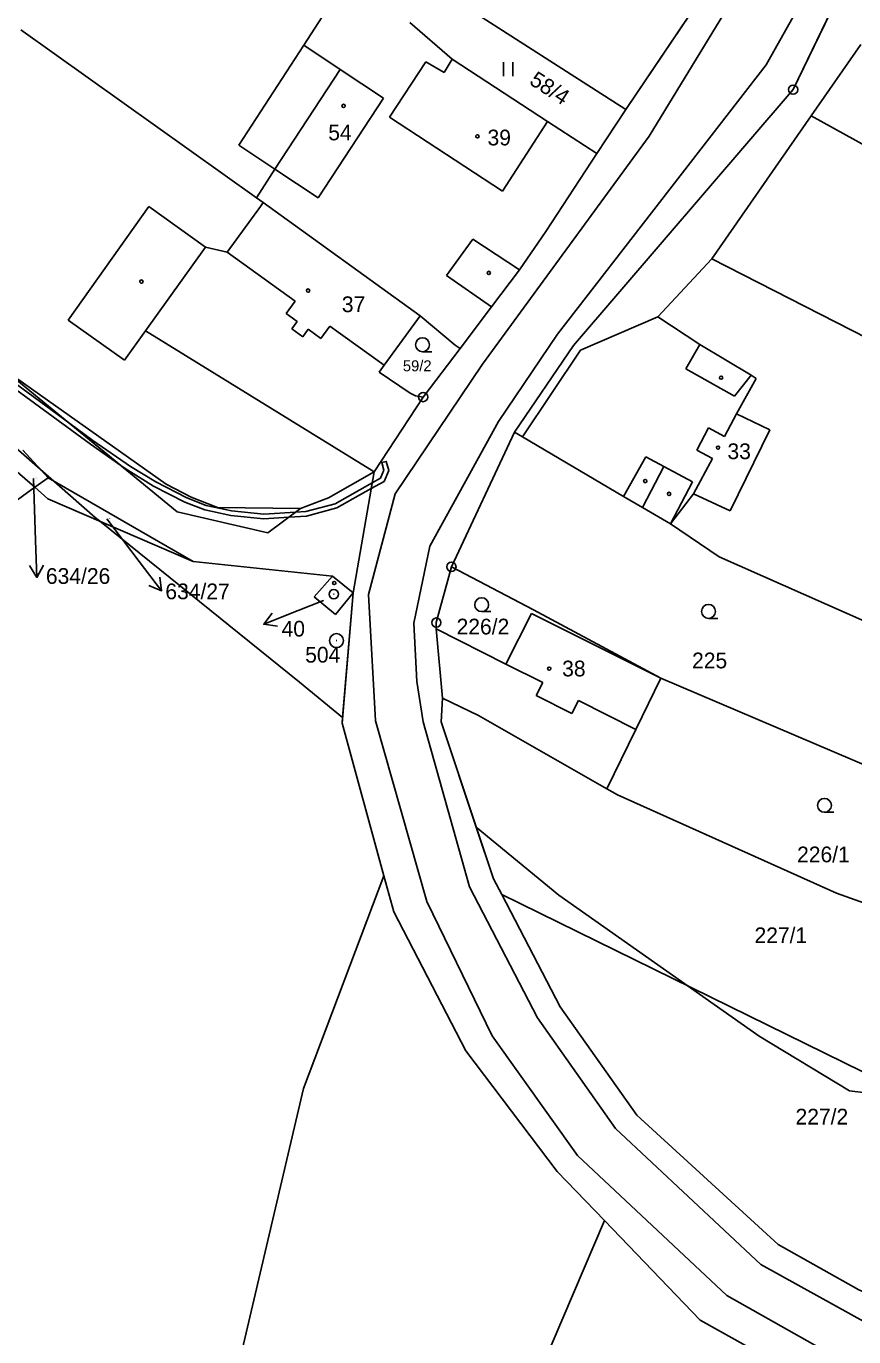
# Model space of a CAD drawing. Extents: x -743888 to -742027, y -1128394 to -1126768.
# Drawn here: x -743087.8 to -742998.5, y -1127789.2 to -1127647.7 of the extents above; entities that cross this region are included whole.
import ezdxf

# ---------------------------------------------------------------- set-up
doc = ezdxf.new("R2010")
doc.units = 0
for name, color, linetype in [('Vrstva 1', 7, 'Continuous'), ('Vrstva 16', 7, 'Continuous'), ('Vrstva 17', 7, 'Continuous'), ('Vrstva 18', 7, 'Continuous'), ('Vrstva 19', 7, 'Continuous'), ('Vrstva 24', 7, 'Continuous'), ('Vrstva 25', 7, 'Continuous'), ('Vrstva 3', 7, 'Continuous'), ('Vrstva 30', 7, 'Continuous'), ('Vrstva 37', 7, 'Continuous'), ('Vrstva 4', 7, 'Continuous'), ('Vrstva 52', 7, 'Continuous'), ('Vrstva 6', 7, 'Continuous')]:
    doc.layers.add(name, color=color, linetype=linetype)

msp = doc.modelspace()

# ---------------------------------------------------------------- linework, layer by layer
at = {"layer": 'Vrstva 1'}
for points in [[(-743005.02, -1127654.54), (-742990.11, -1127623.65)], [(-743023.07, -1127656.68), (-743006.21, -1127631.58)], [(-743057.84, -1127649.75), (-743053.43, -1127642.86)], [(-743041.39, -1127644.94), (-743023.07, -1127656.68)], [(-743088.43, -1127648.09), (-743062.98, -1127666.21)], [(-743046.41, -1127647.29), (-743041.85, -1127651.26)], [(-743064.89, -1127660.55), (-743057.84, -1127649.75)], [(-743057.84, -1127649.75), (-743053.93, -1127652.35)], [(-743003.07, -1127657.38), (-742997.69, -1127649.67)], [(-743053.93, -1127652.35), (-743049.27, -1127655.45)], [(-743041.85, -1127651.26), (-743031.54, -1127657.97)], [(-743028.72, -1127682.17), (-743005.02, -1127654.54)], [(-743056.31, -1127666.21), (-743049.27, -1127655.45)], [(-743026.2, -1127661.44), (-743023.07, -1127656.68)], [(-743031.54, -1127657.97), (-743026.2, -1127661.44)], [(-743013.81, -1127672.8), (-743003.07, -1127657.38)], [(-743064.89, -1127660.55), (-743060.97, -1127663.13)], [(-743031.72, -1127669.85), (-743026.2, -1127661.44)], [(-743062.98, -1127666.21), (-743060.97, -1127663.13)], [(-743060.97, -1127663.13), (-743056.31, -1127666.21)], [(-743062.98, -1127666.21), (-743062.24, -1127666.73)], [(-743062.54, -1127667.14), (-743062.24, -1127666.73)], [(-743062.24, -1127666.73), (-743045.29, -1127678.95)], [(-743083.3, -1127679.41), (-743074.6, -1127667.14)], [(-743074.6, -1127667.14), (-743068.46, -1127671.55)], [(-743066.13, -1127672.07), (-743062.54, -1127667.14)], [(-743034.56, -1127673.98), (-743031.72, -1127669.85)], [(-743068.46, -1127671.55), (-743066.13, -1127672.07)], [(-743019.62, -1127679.08), (-743013.81, -1127672.8)], [(-743013.81, -1127672.8), (-742970.18, -1127695.1)], [(-743037.58, -1127678), (-743034.56, -1127673.98)], [(-743040.96, -1127682.5), (-743037.58, -1127678)], [(-743083.3, -1127679.41), (-743077.21, -1127683.74)], [(-743049.19, -1127684.3), (-743045.58, -1127679.36)], [(-743045.58, -1127679.36), (-743045.29, -1127678.95)], [(-743045.29, -1127678.95), (-743041.53, -1127682.11)], [(-743027.99, -1127682.66), (-743019.62, -1127679.08)], [(-743019.62, -1127679.08), (-743015.08, -1127682.06)], [(-743077.21, -1127683.74), (-743074.95, -1127680.59)], [(-743074.95, -1127680.59), (-743050.26, -1127695.79)], [(-743041.53, -1127682.11), (-743040.96, -1127682.5)], [(-743035.1, -1127691.53), (-743028.72, -1127682.17)], [(-743015.08, -1127682.06), (-743009.56, -1127685.38)], [(-743044.97, -1127687.73), (-743040.96, -1127682.5)], [(-743034.24, -1127692.03), (-743027.99, -1127682.66)], [(-743049.72, -1127685.03), (-743049.19, -1127684.3)], [(-743049.72, -1127685.03), (-743046.39, -1127687.31)], [(-743011.13, -1127689.55), (-743009, -1127685.72)], [(-743009.56, -1127685.38), (-743009, -1127685.72)], [(-743050.26, -1127695.79), (-743044.97, -1127687.73)], [(-743046.39, -1127687.31), (-743045.79, -1127687.59)], [(-743045.79, -1127687.59), (-743044.97, -1127687.73)], [(-743011.13, -1127689.55), (-743007.52, -1127691.27)], [(-743041.92, -1127706.05), (-743035.1, -1127691.53)], [(-743035.1, -1127691.53), (-743034.24, -1127692.03)], [(-743034.24, -1127692.03), (-743023.34, -1127698.47)], [(-743011.82, -1127700.03), (-743007.52, -1127691.27)], [(-743089.62, -1127695.12), (-743086.91, -1127697.47)], [(-743055.21, -1127698.61), (-743050.26, -1127695.79)], [(-743052.52, -1127708.86), (-743050.26, -1127695.79)], [(-743086.91, -1127697.47), (-743085.49, -1127698.7)], [(-743085.49, -1127698.7), (-743069.79, -1127705.5)], [(-743058.22, -1127699.76), (-743055.21, -1127698.61)], [(-743023.34, -1127698.47), (-743021.3, -1127699.65)], [(-743018.27, -1127701.4), (-743015.78, -1127698.17)], [(-743015.78, -1127698.17), (-743011.82, -1127700.03)], [(-743021.3, -1127699.65), (-743018.27, -1127701.4)], [(-743018.27, -1127701.4), (-743013, -1127704.97)], [(-743069.79, -1127705.5), (-743054.75, -1127707.06)], [(-743043.55, -1127712.08), (-743041.92, -1127706.05)], [(-743041.92, -1127706.05), (-743033.05, -1127710.69)], [(-743013, -1127704.97), (-742980.63, -1127719.3)], [(-743056.75, -1127709.3), (-743054.75, -1127707.06)], [(-743054.75, -1127707.06), (-743052.52, -1127708.86)], [(-743054.42, -1127711.2), (-743052.52, -1127708.86)], [(-743053.72, -1127722.94), (-743052.52, -1127708.86)], [(-743056.75, -1127709.3), (-743054.42, -1127711.2)], [(-743036.05, -1127716.56), (-743033.26, -1127711.09)], [(-743033.26, -1127711.09), (-743019.3, -1127718.08)], [(-743033.05, -1127710.69), (-743019.3, -1127718.08)], [(-743043.57, -1127712.76), (-743043.55, -1127712.08)], [(-743043.57, -1127712.76), (-743042.89, -1127720.23)], [(-743043.57, -1127712.76), (-743036.05, -1127716.56)], [(-743022, -1127723.61), (-743019.3, -1127718.08)], [(-743019.3, -1127718.08), (-742986.19, -1127732.18)], [(-743043.04, -1127722.81), (-743042.89, -1127720.23)], [(-743042.89, -1127720.23), (-743039.01, -1127722.1)], [(-743053.72, -1127722.94), (-743049.21, -1127739.41)], [(-743043.04, -1127722.81), (-743037.36, -1127739.74)], [(-743039.01, -1127722.1), (-743025.14, -1127730.02)], [(-743025.14, -1127730.02), (-743022, -1127723.61)], [(-743025.14, -1127730.02), (-743023.98, -1127730.68)], [(-743023.98, -1127730.68), (-743000.34, -1127741.31)], [(-743049.21, -1127739.41), (-743048.14, -1127743.3)], [(-743037.36, -1127739.74), (-743036.47, -1127741.45)], [(-743036.47, -1127741.45), (-743030.16, -1127753.57)], [(-743000.34, -1127741.31), (-742982, -1127747.83)], [(-743048.14, -1127743.3), (-743040.35, -1127758.3)], [(-743030.16, -1127753.57), (-743021.89, -1127765.25)], [(-743040.35, -1127758.3), (-743030.5, -1127771.33)], [(-743021.89, -1127765.25), (-743006.65, -1127779.24)], [(-743030.5, -1127771.33), (-743025.38, -1127776.65)], [(-743025.38, -1127776.65), (-743015.05, -1127787.39)], [(-743006.65, -1127779.24), (-742997.92, -1127784.13)], [(-743015.05, -1127787.39), (-743011.33, -1127789.48)]]:
    msp.add_lwpolyline(points, dxfattribs=at)
at = {"layer": 'Vrstva 16'}
for p, q in [((-743085.97, -1127705.87), (-743086.68, -1127707.2)), ((-743073.4, -1127707.16), (-743073.21, -1127708.65)), ((-743060.7, -1127712.48), (-743062.19, -1127712.26))]:
    msp.add_line(p, q, dxfattribs=at)
for points in [[(-743087.06, -1127696.52), (-743086.82, -1127703.2)], [(-743079.13, -1127700.88), (-743075.63, -1127705.47)], [(-743086.82, -1127703.2), (-743086.68, -1127707.2), (-743087.47, -1127705.93)], [(-743075.63, -1127705.47), (-743073.21, -1127708.65), (-743074.59, -1127708.07)], [(-743055.74, -1127709.69), (-743058.47, -1127710.78)], [(-743058.47, -1127710.78), (-743062.19, -1127712.26), (-743061.26, -1127711.08)]]:
    msp.add_lwpolyline(points, dxfattribs=at)
at = {"layer": 'Vrstva 24'}
for p, q in [((-743005.07, -1127654.54), (-743004.97, -1127654.54)), ((-743045.02, -1127687.73), (-743044.92, -1127687.73)), ((-743041.97, -1127706.05), (-743041.87, -1127706.05)), ((-743054.67, -1127709.01), (-743054.57, -1127709.01)), ((-743043.6, -1127712.08), (-743043.5, -1127712.08)), ((-743054.38, -1127714.03), (-743054.28, -1127714.03))]:
    msp.add_line(p, q, dxfattribs=at)
for centre, radius in [((-743005.02, -1127654.54), 0.499), ((-743044.97, -1127687.73), 0.499), ((-743041.92, -1127706.05), 0.499), ((-743054.62, -1127709.01), 0.499), ((-743043.55, -1127712.08), 0.499), ((-743054.33, -1127714.03), 0.756)]:
    msp.add_circle(centre, radius, dxfattribs=at)
at = {"layer": 'Vrstva 25'}
for p, q in [((-743036.3, -1127651.57), (-743036.3, -1127653.07)), ((-743035.3, -1127653.07), (-743035.3, -1127651.57)), ((-743045.04, -1127682.83), (-743044.04, -1127682.83)), ((-743038.65, -1127710.9), (-743037.65, -1127710.9)), ((-743014.16, -1127711.62), (-743013.16, -1127711.62)), ((-743001.64, -1127732.56), (-743000.64, -1127732.56))]:
    msp.add_line(p, q, dxfattribs=at)
for centre, radius in [((-743053.56, -1127656.29), 0.175), ((-743039.11, -1127659.58), 0.175), ((-743075.39, -1127675.26), 0.175), ((-743037.88, -1127674.33), 0.175), ((-743057.4, -1127676.23), 0.175), ((-743045.04, -1127682.08), 0.75), ((-743012.8, -1127685.64), 0.175), ((-743013.13, -1127693.19), 0.175), ((-743020.99, -1127696.8), 0.175), ((-743018.41, -1127698.19), 0.175), ((-743054.57, -1127707.81), 0.175), ((-743038.65, -1127710.15), 0.75), ((-743014.16, -1127710.87), 0.75), ((-743031.36, -1127717.05), 0.175), ((-743001.64, -1127731.81), 0.75)]:
    msp.add_circle(centre, radius, dxfattribs=at)
at = {"layer": 'Vrstva 3'}
for points in [[(-743060.97, -1127663.13), (-743053.93, -1127652.35)], [(-743053.93, -1127652.35), (-743049.27, -1127655.45)], [(-743048.61, -1127657.52), (-743044.69, -1127651.52)], [(-743044.69, -1127651.52), (-743042.7, -1127652.7)], [(-743042.7, -1127652.7), (-743041.85, -1127651.26)], [(-743041.85, -1127651.26), (-743031.54, -1127657.97)], [(-743056.31, -1127666.21), (-743049.27, -1127655.45)], [(-743048.61, -1127657.52), (-743036.42, -1127665.5)], [(-743036.42, -1127665.5), (-743031.54, -1127657.97)], [(-743060.97, -1127663.13), (-743056.31, -1127666.21)], [(-743062.54, -1127667.14), (-743062.24, -1127666.73)], [(-743062.24, -1127666.73), (-743045.29, -1127678.95)], [(-743066.13, -1127672.07), (-743062.54, -1127667.14)], [(-743066.13, -1127672.07), (-743058.8, -1127677.37)], [(-743059.75, -1127678.69), (-743058.8, -1127677.37)], [(-743059.75, -1127678.69), (-743058.57, -1127679.56)], [(-743049.19, -1127684.3), (-743045.58, -1127679.36)], [(-743045.58, -1127679.36), (-743045.29, -1127678.95)], [(-743059.15, -1127680.38), (-743058.57, -1127679.56)], [(-743059.15, -1127680.38), (-743057.98, -1127681.22)], [(-743057.98, -1127681.22), (-743057.39, -1127680.41)], [(-743057.39, -1127680.41), (-743056.02, -1127681.41)], [(-743056.02, -1127681.41), (-743055.05, -1127680.07)], [(-743055.05, -1127680.07), (-743049.19, -1127684.3)], [(-743012.44, -1127691.97), (-743011.13, -1127689.55)], [(-743011.13, -1127689.55), (-743007.52, -1127691.27)], [(-743015.4, -1127693.46), (-743014.15, -1127691.05)], [(-743014.15, -1127691.05), (-743012.44, -1127691.97)], [(-743011.82, -1127700.03), (-743007.52, -1127691.27)], [(-743015.4, -1127693.46), (-743013.73, -1127694.36)], [(-743015.78, -1127698.17), (-743013.73, -1127694.36)], [(-743015.78, -1127698.17), (-743011.82, -1127700.03)], [(-743056.75, -1127709.3), (-743054.75, -1127707.06)], [(-743054.75, -1127707.06), (-743052.52, -1127708.86)], [(-743054.42, -1127711.2), (-743052.52, -1127708.86)], [(-743056.75, -1127709.3), (-743054.42, -1127711.2)], [(-743036.05, -1127716.56), (-743033.26, -1127711.09)], [(-743033.26, -1127711.09), (-743019.3, -1127718.08)], [(-743036.05, -1127716.56), (-743032.05, -1127718.56)], [(-743032.75, -1127719.95), (-743032.05, -1127718.56)], [(-743022, -1127723.61), (-743019.3, -1127718.08)], [(-743032.75, -1127719.95), (-743028.9, -1127721.9)], [(-743028.9, -1127721.9), (-743028.19, -1127720.5)], [(-743028.19, -1127720.5), (-743022, -1127723.61)]]:
    msp.add_lwpolyline(points, dxfattribs=at)
at = {"layer": 'Vrstva 30'}
for points in [[(-743122.26, -1127659.74), (-743126.67, -1127656.02), (-743123.24, -1127658.26), (-743121.94, -1127659.36), (-743113.07, -1127666.17), (-743106.5, -1127671.8), (-743105.74, -1127672.45), (-743099.92, -1127677.43), (-743092.17, -1127683.97), (-743083.13, -1127690.59), (-743077.63, -1127695.11), (-743080.91, -1127692.83), (-743092.47, -1127684.37), (-743100.18, -1127677.94), (-743106.35, -1127672.62), (-743106.35, -1127672.32), (-743106.65, -1127672.28), (-743113.44, -1127666.65), (-743122.26, -1127659.74)], [(-743080.63, -1127692.43), (-743076.58, -1127695.22), (-743073.85, -1127696.9), (-743070.49, -1127698.62), (-743068.4, -1127699.44), (-743065.67, -1127700.01), (-743062.18, -1127700.38), (-743058.75, -1127700.16), (-743059.48, -1127700.7), (-743062.18, -1127700.88), (-743065.75, -1127700.51), (-743068.54, -1127699.92), (-743070.69, -1127699.08), (-743074.09, -1127697.34), (-743076.86, -1127695.64), (-743077.63, -1127695.11), (-743083.13, -1127690.59), (-743080.63, -1127692.43)], [(-743050.47, -1127696.99), (-743049.59, -1127696.49), (-743049.21, -1127695.63), (-743049.44, -1127694.81), (-743048.96, -1127694.67), (-743048.67, -1127695.67), (-743049.19, -1127696.85), (-743050.58, -1127697.62), (-743050.47, -1127696.99)], [(-743058.75, -1127700.16), (-743057.63, -1127700.08), (-743054.47, -1127699.24), (-743050.47, -1127696.99), (-743050.58, -1127697.62), (-743054.29, -1127699.7), (-743057.55, -1127700.58), (-743059.48, -1127700.7), (-743058.75, -1127700.16)]]:
    msp.add_lwpolyline(points, dxfattribs=at)
at = {"layer": 'Vrstva 37'}
for centre in [(-743053.56, -1127656.29), (-743039.11, -1127659.58), (-743057.4, -1127676.23), (-743013.13, -1127693.19), (-743054.57, -1127707.81), (-743031.36, -1127717.05)]:
    msp.add_circle(centre, 0.175, dxfattribs=at)
at = {"layer": 'Vrstva 4'}
for points in [[(-743020.57, -1127659.55), (-742994.19, -1127616.32)], [(-743007.93, -1127651.85), (-742989.42, -1127618.93)], [(-743060.97, -1127663.13), (-743053.93, -1127652.35)], [(-743048.61, -1127657.52), (-743044.69, -1127651.52)], [(-743044.69, -1127651.52), (-743042.7, -1127652.7)], [(-743042.7, -1127652.7), (-743041.85, -1127651.26)], [(-743030.45, -1127680.95), (-743007.93, -1127651.85)], [(-743048.61, -1127657.52), (-743036.42, -1127665.5)], [(-743036.42, -1127665.5), (-743031.54, -1127657.97)], [(-743038.55, -1127684.18), (-743020.57, -1127659.55)], [(-743042.45, -1127674.62), (-743039.6, -1127670.68)], [(-743039.6, -1127670.68), (-743034.56, -1127673.98)], [(-743074.95, -1127680.59), (-743068.46, -1127671.55)], [(-743066.13, -1127672.07), (-743058.8, -1127677.37)], [(-743042.45, -1127674.62), (-743037.58, -1127678)], [(-743059.75, -1127678.69), (-743058.8, -1127677.37)], [(-743059.75, -1127678.69), (-743058.57, -1127679.56)], [(-743059.15, -1127680.38), (-743058.57, -1127679.56)], [(-743059.15, -1127680.38), (-743057.98, -1127681.22)], [(-743057.98, -1127681.22), (-743057.39, -1127680.41)], [(-743057.39, -1127680.41), (-743056.02, -1127681.41)], [(-743056.02, -1127681.41), (-743055.05, -1127680.07)], [(-743055.05, -1127680.07), (-743049.19, -1127684.3)], [(-743036.85, -1127690.37), (-743030.45, -1127680.95)], [(-743016.62, -1127684.69), (-743015.08, -1127682.06)], [(-743090.48, -1127684.56), (-743072.72, -1127697.13)], [(-743047.98, -1127698.19), (-743038.55, -1127684.18)], [(-743016.62, -1127684.69), (-743011.36, -1127687.63)], [(-743011.36, -1127687.63), (-743009.56, -1127685.38)], [(-743044.25, -1127703.82), (-743036.85, -1127690.37)], [(-743012.44, -1127691.97), (-743011.13, -1127689.55)], [(-743015.4, -1127693.46), (-743014.15, -1127691.05)], [(-743014.15, -1127691.05), (-743012.44, -1127691.97)], [(-743015.4, -1127693.46), (-743013.73, -1127694.36)], [(-743023.34, -1127698.47), (-743020.92, -1127694.17)], [(-743020.92, -1127694.17), (-743018.97, -1127695.22)], [(-743015.78, -1127698.17), (-743013.73, -1127694.36)], [(-743021.3, -1127699.65), (-743018.97, -1127695.22)], [(-743018.97, -1127695.22), (-743015.9, -1127696.88)], [(-743072.72, -1127697.13), (-743070.01, -1127698.54)], [(-743018.27, -1127701.4), (-743015.9, -1127696.88)], [(-743070.01, -1127698.54), (-743067.17, -1127699.66)], [(-743050.88, -1127709.04), (-743047.98, -1127698.19)], [(-743067.17, -1127699.66), (-743058.22, -1127699.76)], [(-743045.96, -1127712.14), (-743044.25, -1127703.82)], [(-743050.88, -1127709.04), (-743050.12, -1127722.67)], [(-743045.96, -1127712.14), (-743045.67, -1127718.43)], [(-743036.05, -1127716.56), (-743032.05, -1127718.56)], [(-743045.67, -1127718.43), (-743044.96, -1127722.78)], [(-743032.75, -1127719.95), (-743032.05, -1127718.56)], [(-743032.75, -1127719.95), (-743028.9, -1127721.9)], [(-743028.9, -1127721.9), (-743028.19, -1127720.5)], [(-743028.19, -1127720.5), (-743022, -1127723.61)], [(-743050.12, -1127722.67), (-743044.56, -1127742.19)], [(-743044.96, -1127722.78), (-743039.98, -1127740.62)], [(-743039.98, -1127740.62), (-743032.62, -1127754.77)], [(-743044.56, -1127742.19), (-743037.53, -1127756.7)], [(-743032.62, -1127754.77), (-743024.19, -1127766.7)], [(-743037.53, -1127756.7), (-743028.31, -1127769.6)], [(-743024.19, -1127766.7), (-743008.52, -1127781.37)], [(-743028.31, -1127769.6), (-743012.17, -1127784.72)], [(-743008.52, -1127781.37), (-742992.69, -1127790.12)], [(-743012.17, -1127784.72), (-742994.83, -1127794.53)]]:
    msp.add_lwpolyline(points, dxfattribs=at)
at = {"layer": 'Vrstva 52'}
for points in [[(-743053.67, -1127722.32), (-743058.31, -1127718.5), (-743079.93, -1127701.11), (-743080.38, -1127700.75), (-743105, -1127679.13), (-743127.88, -1127660), (-743130, -1127657.5), (-743148.25, -1127642.13), (-743183.06, -1127617.63), (-743185.22, -1127616.53), (-743196.63, -1127610.75), (-743212.31, -1127605.25), (-743222.5, -1127604.38), (-743235.19, -1127605.75), (-743244.13, -1127607.38), (-743252.19, -1127610.75), (-743260.69, -1127617.13), (-743270.44, -1127627.38), (-743275.94, -1127635), (-743280.63, -1127645.13), (-743281.88, -1127655.38), (-743283.19, -1127657.88), (-743283.56, -1127673.13), (-743282.53, -1127677.41)], [(-743053.67, -1127722.32), (-743052.52, -1127708.86), (-743050.26, -1127695.79), (-743044.97, -1127687.73), (-743040.96, -1127682.5), (-743037.58, -1127678), (-743034.56, -1127673.98), (-743031.72, -1127669.85), (-743026.2, -1127661.44), (-743023.07, -1127656.68), (-743014.19, -1127643.46)], [(-742999.9, -1127643.94), (-743005.02, -1127654.54), (-743028.72, -1127682.17), (-743035.1, -1127691.53), (-743041.92, -1127706.05), (-743043.55, -1127712.08), (-743043.57, -1127712.76), (-743042.89, -1127720.23), (-743043.04, -1127722.81), (-743039.23, -1127734.18)], [(-743053.67, -1127722.32), (-743053.72, -1127722.94), (-743049.21, -1127739.41), (-743048.14, -1127743.3), (-743040.35, -1127758.3), (-743030.5, -1127771.33), (-743025.38, -1127776.65), (-743015.05, -1127787.39), (-743011.33, -1127789.48), (-742996.28, -1127797.93), (-742982.41, -1127802.98), (-742971.25, -1127807.04), (-742969.31, -1127807.66), (-742941.27, -1127816.58), (-742913.36, -1127825.45), (-742905.98, -1127827.8), (-742901.58, -1127829.29), (-742887.63, -1127833.99), (-742883.39, -1127836.13), (-742870.31, -1127842.73), (-742866.75, -1127845.26), (-742862.04, -1127848.59)], [(-743039.23, -1127734.18), (-743030.31, -1127741.5), (-743008.69, -1127756.75), (-742998.94, -1127762.63), (-742981.5, -1127764.75), (-742969.25, -1127763.5), (-742946.75, -1127755), (-742935.69, -1127749.13), (-742914.06, -1127739.38), (-742905.56, -1127736.38), (-742887.75, -1127733), (-742875.44, -1127732.5), (-742855.5, -1127738.88), (-742848.75, -1127745.25), (-742840.69, -1127757.63), (-742837.69, -1127765.63), (-742836, -1127779.25), (-742838.13, -1127798.75), (-742839.81, -1127808.88), (-742842.81, -1127819.13), (-742849.56, -1127831.75), (-742855.17, -1127839.32)], [(-743039.23, -1127734.18), (-743037.36, -1127739.74), (-743036.47, -1127741.45), (-743030.16, -1127753.57), (-743021.89, -1127765.25), (-743006.65, -1127779.24), (-742997.92, -1127784.13), (-742991.64, -1127786.82), (-742967.48, -1127795.61), (-742902.77, -1127815.89), (-742889.66, -1127821.18), (-742882.56, -1127824.07), (-742864.61, -1127832.85), (-742855.17, -1127839.32)]]:
    msp.add_lwpolyline(points, dxfattribs=at)
at = {"layer": 'Vrstva 6'}
for points in [[(-743003.07, -1127657.38), (-742986.2, -1127666.67)], [(-743090.48, -1127684.56), (-743071.53, -1127700.11)], [(-743088.2, -1127693.47), (-743085.48, -1127696.45)], [(-743090.95, -1127700.36), (-743086.91, -1127697.47)], [(-743086.91, -1127697.47), (-743085.48, -1127696.45)], [(-743085.48, -1127696.45), (-743069.79, -1127705.5)], [(-743071.53, -1127700.11), (-743061.74, -1127702.4)], [(-743061.74, -1127702.4), (-743058.22, -1127699.76)], [(-743057.88, -1127762.39), (-743049.21, -1127739.41)], [(-743036.47, -1127741.45), (-742989.35, -1127764.58)], [(-743081.3, -1127862.06), (-743057.88, -1127762.39)], [(-743032.09, -1127792.31), (-743025.38, -1127776.65)]]:
    msp.add_lwpolyline(points, dxfattribs=at)

# ---------------------------------------------------------------- texts
at = {"layer": 'Vrstva 16'}
for s, p in [('634/26', (-743085.71, -1127707.9)), ('634/27', (-743072.81, -1127709.56)), ('40', (-743060.26, -1127713.59))]:
    msp.add_text(s, height=1.7, dxfattribs=at).set_placement(p)
at = {"layer": 'Vrstva 17'}
msp.add_text('504', height=1.7, dxfattribs=at).set_placement((-743057.71, -1127716.4))
at = {"layer": 'Vrstva 18'}
msp.add_text('58/4', height=1.7, rotation=327.1406, dxfattribs=at).set_placement((-743033.61, -1127653.88))
for s, height, p in [('59/2', 1.19, (-743047.16, -1127684.95)), ('634/26', 0.1, (-743087.06, -1127696.52)), ('634/27', 0.1, (-743079.13, -1127700.88)), ('226/2', 1.7, (-743041.36, -1127713.36)), ('225', 1.7, (-743015.93, -1127717.02)), ('226/1', 1.7, (-743004.59, -1127737.96)), ('227/1', 1.7, (-743009.19, -1127746.69)), ('227/2', 1.7, (-743004.76, -1127766.27))]:
    msp.add_text(s, height=height, dxfattribs=at).set_placement(p)
at = {"layer": 'Vrstva 19'}
for s, height, p in [('54', 1.7, (-743055.22, -1127660.01)), ('39', 1.7, (-743038.02, -1127660.56)), ('37', 1.7, (-743053.75, -1127678.56)), ('33', 1.7, (-743012.11, -1127694.43)), ('40', 0.1, (-743055.74, -1127709.69)), ('38', 1.7, (-743029.96, -1127717.89))]:
    msp.add_text(s, height=height, dxfattribs=at).set_placement(p)

doc.saveas('drawing.dxf')
